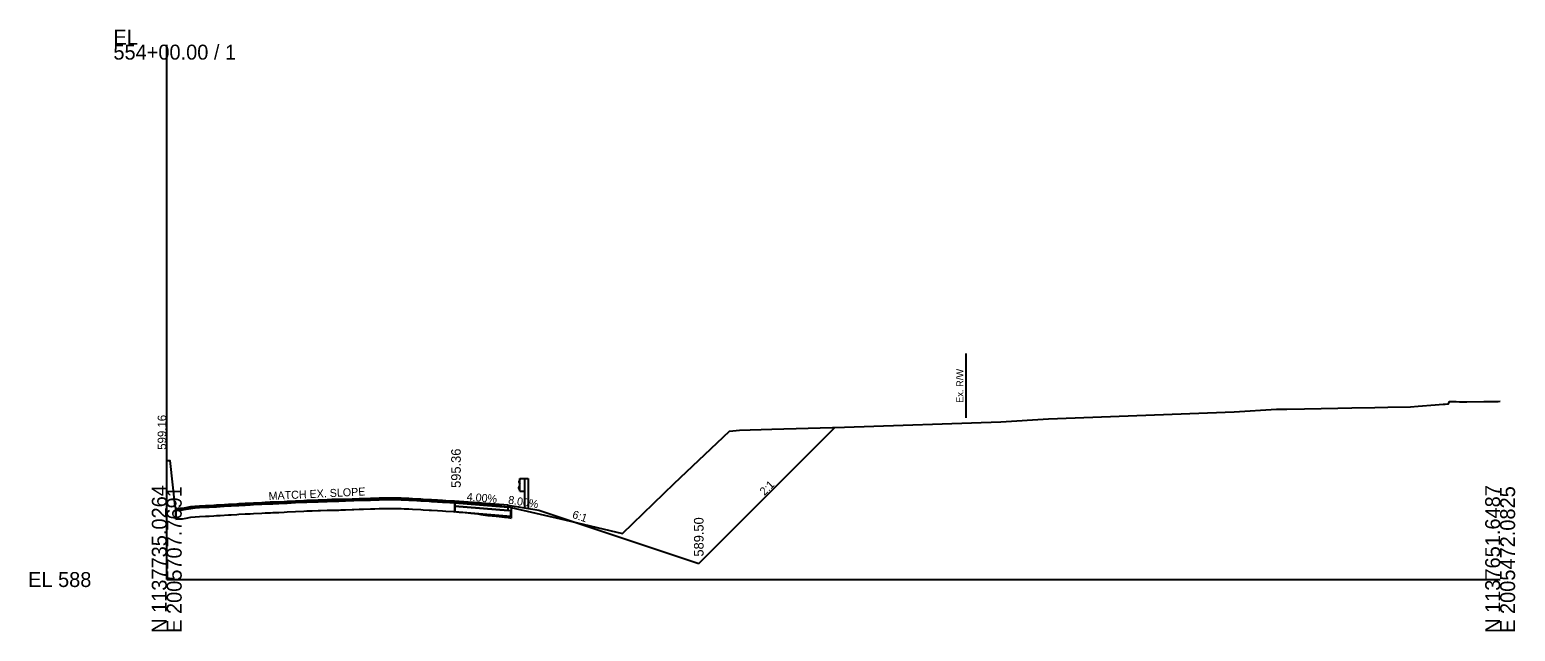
# Model space of a CAD drawing. Extents: x -201 to 2007062, y -213 to 1139737.
# Drawn here: x -25.7 to 252.8, y 7990.3 to 8103 of the extents above; entities that cross this region are included whole.
import ezdxf

# ---------------------------------------------------------------- set-up
doc = ezdxf.new("R2010")
doc.units = 0
for name, color, linetype in [('Default', 7, 'Continuous'), ('RD_GPK_XS_Cell', 7, 'Continuous'), ('RD_Sketch1', 7, 'Continuous'), ('RD_XS_Base', 7, 'Continuous'), ('RD_XS_EarthShd', 7, 'Continuous'), ('RD_XS_ExGround', 7, 'Continuous'), ('RD_XS_ExPaveRet', 7, 'Continuous'), ('RD_XS_ExRW', 7, 'Continuous'), ('RD_XS_GR', 7, 'Continuous'), ('RD_XS_PaveOvlay', 7, 'Continuous'), ('RD_XS_PaveShd', 7, 'Continuous'), ('RD_XS_TieSlope', 7, 'Continuous'), ('RD_XS_TX_Ditch', 7, 'Continuous'), ('RD_XS_TX_Elev_EX', 7, 'Continuous'), ('RD_XS_TX_Elev_PR', 7, 'Continuous'), ('RD_XS_TX_Slope', 7, 'Continuous')]:
    doc.layers.add(name, color=color, linetype=linetype)

msp = doc.modelspace()

# ---------------------------------------------------------------- linework, layer by layer
at = {"layer": 'RD_GPK_XS_Cell'}
for q in [(0, 8100.22), (250, 8000)]:
    msp.add_line((0, 8000), q, dxfattribs=at)
at = {"layer": 'RD_XS_Base'}
for points in [[(64, 8013.58), (54, 8014.38)], [(54, 8014.38), (54, 8013.72)], [(64.5, 8012.88), (64, 8012.92), (54, 8013.72)], [(54, 8013.72), (54, 8012.72)], [(54, 8013.72), (64, 8012.92)], [(64, 8012.92), (64, 8013.58)], [(54, 8012.72), (64.5, 8011.88)], [(64.5, 8011.88), (64.5, 8012.88)]]:
    msp.add_lwpolyline(points, dxfattribs=at)
at = {"layer": 'RD_XS_EarthShd'}
msp.add_lwpolyline([(64, 8013.91), (69.75, 8012.99)], dxfattribs=at)
at = {"layer": 'RD_XS_ExGround'}
msp.add_lwpolyline([(0, 8022.31), (0.57, 8022.33), (1.52, 8013.72), (1.68, 8013.32), (2.13, 8013.35), (2.94, 8013.39), (3.62, 8013.52), (4.52, 8013.66), (5.32, 8013.76), (6.11, 8013.8), (7.27, 8013.86), (7.97, 8013.9), (8.82, 8013.94), (9.3, 8013.97), (10.03, 8014.02), (11.59, 8014.11), (12.07, 8014.14), (13.16, 8014.21), (13.54, 8014.24), (14.73, 8014.29), (15.67, 8014.33), (16.29, 8014.37), (17.83, 8014.46), (18.45, 8014.51), (19.12, 8014.51), (19.43, 8014.53), (19.91, 8014.55), (21, 8014.58), (22.03, 8014.63), (22.56, 8014.66), (24.15, 8014.76), (25.7, 8014.84), (26.27, 8014.86), (27.26, 8014.88), (28.39, 8014.93), (28.83, 8014.94), (30.06, 8014.98), (30.48, 8015), (30.98, 8015.03), (32.25, 8015.03), (32.64, 8015.05), (33.53, 8015.09), (34.76, 8015.13), (35.1, 8015.14), (36.06, 8015.18), (36.88, 8015.21), (38.23, 8015.23), (39, 8015.25), (39.8, 8015.29), (41.37, 8015.31), (42.17, 8015.33), (42.49, 8015.34), (43.08, 8015.34), (43.97, 8015.29), (44.5, 8015.26), (45.37, 8015.22), (46.07, 8015.18), (47.64, 8015.1), (48.05, 8015.07), (49.2, 8015), (49.61, 8014.98), (50.77, 8014.92), (51.73, 8014.85), (52.34, 8014.81), (53.85, 8014.72), (54.8, 8014.65), (55.24, 8014.61), (55.97, 8014.56), (57.03, 8014.45), (58.3, 8014.32), (58.88, 8014.2), (60.22, 8014), (61.74, 8013.89), (62.34, 8013.83), (63.31, 8013.7), (64.03, 8013.61), (64.6, 8013.51), (74.66, 8011.16), (85.46, 8008.65), (95.15, 8018.02), (105.52, 8027.8), (107.41, 8027.99), (113.47, 8028.18), (127.06, 8028.55), (156.4, 8029.55), (165.31, 8030.11), (200.12, 8031.41), (208.06, 8031.9), (208.65, 8031.91), (209.36, 8031.92), (210.02, 8031.94), (213.3, 8032), (219.58, 8032.11), (222.18, 8032.16), (226.5, 8032.24), (228.92, 8032.28), (233.22, 8032.36), (234.63, 8032.47), (237.8, 8032.72), (239.34, 8032.84), (239.7, 8032.87), (240.34, 8032.92), (240.51, 8033.35), (241.23, 8033.35), (241.76, 8033.34), (242.35, 8033.32), (243.16, 8033.28), (243.73, 8033.27), (246.94, 8033.34), (247.58, 8033.33), (249.6, 8033.39), (250, 8033.41)], dxfattribs=at)
at = {"layer": 'RD_XS_ExPaveRet'}
for p, q in [((54, 8013.72), (54, 8014.38)), ((54, 8014.38), (54, 8014.38)), ((54, 8012.72), (54, 8013.72)), ((64.6, 8013.51), (64.6, 8011.51)), ((1.68, 8011.32), (1.68, 8013.32)), ((1.68, 8012.99), (1.68, 8011.32)), ((1.68, 8012.99), (1.68, 8012.99)), ((1.68, 8011.32), (2.13, 8011.35)), ((1.68, 8011.32), (2.13, 8011.35)), ((1.68, 8011.32), (1.68, 8011.32)), ((2.13, 8011.35), (2.94, 8011.39)), ((2.13, 8011.35), (2.94, 8011.39)), ((2.94, 8011.39), (3.62, 8011.52)), ((2.94, 8011.39), (3.62, 8011.52)), ((3.62, 8011.52), (4.52, 8011.66)), ((3.62, 8011.52), (4.52, 8011.66)), ((4.52, 8011.66), (5.32, 8011.76)), ((4.52, 8011.66), (5.32, 8011.76)), ((5.32, 8011.76), (6.11, 8011.8)), ((5.32, 8011.76), (6.11, 8011.8)), ((6.11, 8011.8), (7.27, 8011.86)), ((6.11, 8011.8), (7.27, 8011.86)), ((7.27, 8011.86), (7.97, 8011.9)), ((7.27, 8011.86), (7.97, 8011.9)), ((7.97, 8011.9), (8.82, 8011.94)), ((7.97, 8011.9), (8.82, 8011.94)), ((8.82, 8011.94), (9.3, 8011.97)), ((8.82, 8011.94), (9.3, 8011.97)), ((9.3, 8011.97), (10.03, 8012.02)), ((9.3, 8011.97), (10.03, 8012.02)), ((10.03, 8012.02), (11.59, 8012.11)), ((10.03, 8012.02), (11.59, 8012.11)), ((11.59, 8012.11), (12.07, 8012.14)), ((11.59, 8012.11), (12.07, 8012.14)), ((12.07, 8012.14), (13.16, 8012.21)), ((12.07, 8012.14), (13.16, 8012.21)), ((13.16, 8012.21), (13.54, 8012.24)), ((13.16, 8012.21), (13.54, 8012.24)), ((13.54, 8012.24), (14.73, 8012.29)), ((13.54, 8012.24), (14.73, 8012.29)), ((14.73, 8012.29), (15.67, 8012.33)), ((14.73, 8012.29), (15.67, 8012.33)), ((15.67, 8012.33), (16.29, 8012.37)), ((15.67, 8012.33), (16.29, 8012.37)), ((16.29, 8012.37), (17.83, 8012.46)), ((16.29, 8012.37), (17.83, 8012.46)), ((17.83, 8012.46), (18.45, 8012.51)), ((17.83, 8012.46), (18.45, 8012.51)), ((18.45, 8012.51), (19.12, 8012.51)), ((18.45, 8012.51), (19.12, 8012.51)), ((19.12, 8012.51), (19.43, 8012.53)), ((19.12, 8012.51), (19.43, 8012.53)), ((19.43, 8012.53), (19.91, 8012.55)), ((19.43, 8012.53), (19.91, 8012.55)), ((19.91, 8012.55), (21, 8012.58)), ((19.91, 8012.55), (21, 8012.58)), ((21, 8012.58), (22.03, 8012.63)), ((21, 8012.58), (22.03, 8012.63)), ((22.03, 8012.63), (22.56, 8012.66)), ((22.03, 8012.63), (22.56, 8012.66)), ((22.56, 8012.66), (24.15, 8012.76)), ((22.56, 8012.66), (24.15, 8012.76)), ((24.15, 8012.76), (25.7, 8012.84)), ((24.15, 8012.76), (25.7, 8012.84)), ((25.7, 8012.84), (26.27, 8012.86)), ((25.7, 8012.84), (26.27, 8012.86)), ((26.27, 8012.86), (27.26, 8012.88)), ((26.27, 8012.86), (27.26, 8012.88)), ((27.26, 8012.88), (28.39, 8012.93)), ((27.26, 8012.88), (28.39, 8012.93)), ((28.39, 8012.93), (28.83, 8012.94)), ((28.39, 8012.93), (28.83, 8012.94)), ((28.83, 8012.94), (30.06, 8012.98)), ((28.83, 8012.94), (30.06, 8012.98)), ((30.06, 8012.98), (30.48, 8013)), ((30.06, 8012.98), (30.48, 8013)), ((30.48, 8013), (30.98, 8013.03)), ((30.48, 8013), (30.98, 8013.03)), ((30.98, 8013.03), (32.25, 8013.03)), ((30.98, 8013.03), (32.25, 8013.03)), ((32.25, 8013.03), (32.64, 8013.05)), ((32.25, 8013.03), (32.64, 8013.05)), ((32.64, 8013.05), (33.53, 8013.09)), ((32.64, 8013.05), (33.53, 8013.09)), ((33.53, 8013.09), (34.76, 8013.13)), ((33.53, 8013.09), (34.76, 8013.13)), ((34.76, 8013.13), (35.1, 8013.14)), ((34.76, 8013.13), (35.1, 8013.14)), ((35.1, 8013.14), (36.06, 8013.18)), ((35.1, 8013.14), (36.06, 8013.18)), ((36.06, 8013.18), (36.88, 8013.21)), ((36.06, 8013.18), (36.88, 8013.21)), ((36.88, 8013.21), (38.23, 8013.23)), ((36.88, 8013.21), (38.23, 8013.23)), ((38.23, 8013.23), (39, 8013.25)), ((38.23, 8013.23), (39, 8013.25)), ((39, 8013.25), (39.8, 8013.29)), ((39, 8013.25), (39.8, 8013.29)), ((39.8, 8013.29), (41.37, 8013.31)), ((39.8, 8013.29), (41.37, 8013.31)), ((41.37, 8013.31), (42.17, 8013.33)), ((41.37, 8013.31), (42.17, 8013.33)), ((42.17, 8013.33), (42.49, 8013.34)), ((42.17, 8013.33), (42.49, 8013.34)), ((42.49, 8013.34), (43.08, 8013.34)), ((42.49, 8013.34), (43.08, 8013.34)), ((43.08, 8013.34), (43.97, 8013.29)), ((43.08, 8013.34), (43.97, 8013.29)), ((43.97, 8013.29), (44.5, 8013.26)), ((43.97, 8013.29), (44.5, 8013.26)), ((44.5, 8013.26), (45.37, 8013.22)), ((44.5, 8013.26), (45.37, 8013.22)), ((45.37, 8013.22), (46.07, 8013.18)), ((45.37, 8013.22), (46.07, 8013.18)), ((46.07, 8013.18), (47.64, 8013.1)), ((46.07, 8013.18), (47.64, 8013.1)), ((47.64, 8013.1), (48.05, 8013.07)), ((47.64, 8013.1), (48.05, 8013.07)), ((48.05, 8013.07), (49.2, 8013)), ((48.05, 8013.07), (49.2, 8013)), ((49.2, 8013), (49.61, 8012.98)), ((49.2, 8013), (49.61, 8012.98)), ((49.61, 8012.98), (50.77, 8012.92)), ((49.61, 8012.98), (50.77, 8012.92)), ((50.77, 8012.92), (51.73, 8012.85)), ((50.77, 8012.92), (51.73, 8012.85)), ((51.73, 8012.85), (52.34, 8012.81)), ((51.73, 8012.85), (52.34, 8012.81)), ((52.34, 8012.81), (53.85, 8012.72)), ((52.34, 8012.81), (53.85, 8012.72)), ((53.85, 8012.72), (54.8, 8012.65)), ((53.85, 8012.72), (54, 8012.71)), ((54, 8012.72), (54, 8012.71)), ((54, 8012.71), (54, 8012.72)), ((54.8, 8012.65), (55.24, 8012.61)), ((55.24, 8012.61), (55.97, 8012.56)), ((55.97, 8012.56), (57.03, 8012.45)), ((57.03, 8012.45), (58.3, 8012.32)), ((58.3, 8012.32), (58.88, 8012.2)), ((58.88, 8012.2), (60.22, 8012)), ((60.22, 8012), (61.74, 8011.89)), ((61.74, 8011.89), (62.34, 8011.83)), ((62.34, 8011.83), (63.31, 8011.7)), ((63.31, 8011.7), (64.03, 8011.61)), ((64.03, 8011.61), (64.6, 8011.51))]:
    msp.add_line(p, q, dxfattribs=at)
msp.add_lwpolyline([(54, 8014.38), (53.85, 8014.39), (52.34, 8014.47), (51.73, 8014.51), (50.77, 8014.59), (49.61, 8014.65), (49.2, 8014.67), (48.05, 8014.74), (47.64, 8014.77), (46.07, 8014.85), (45.37, 8014.88), (44.5, 8014.93), (43.97, 8014.96), (43.08, 8015.01), (42.49, 8015), (42.17, 8015), (41.37, 8014.98), (39.8, 8014.95), (39, 8014.92), (38.23, 8014.9), (36.88, 8014.88), (36.06, 8014.85), (35.1, 8014.81), (34.76, 8014.8), (33.53, 8014.76), (32.64, 8014.72), (32.25, 8014.7), (30.98, 8014.7), (30.48, 8014.66), (30.06, 8014.65), (28.83, 8014.61), (28.39, 8014.59), (27.26, 8014.54), (26.27, 8014.52), (25.7, 8014.5), (24.15, 8014.43), (22.56, 8014.32), (22.03, 8014.29), (21, 8014.25), (19.91, 8014.21), (19.43, 8014.2), (19.12, 8014.18), (18.45, 8014.18), (17.83, 8014.13), (16.29, 8014.03), (15.67, 8014), (14.73, 8013.95), (13.54, 8013.9), (13.16, 8013.88), (12.07, 8013.81), (11.59, 8013.78), (10.03, 8013.69), (9.3, 8013.64), (8.82, 8013.61), (7.97, 8013.57), (7.27, 8013.53), (6.11, 8013.47), (5.32, 8013.43), (4.52, 8013.33), (3.62, 8013.19), (2.94, 8013.06), (2.13, 8013.01), (1.68, 8012.99)], dxfattribs=at)
at = {"layer": 'RD_XS_ExRW'}
msp.add_line((149.85, 8042.33), (149.85, 8030.33), dxfattribs=at)
at = {"layer": 'RD_XS_GR'}
for p, q in [((66.17, 8018.76), (66, 8018.36)), ((66, 8018.36), (66, 8018.26)), ((66, 8018.26), (66.17, 8017.86)), ((66, 8017.22), (66.17, 8017.62)), ((66, 8017.12), (66, 8017.22)), ((66.17, 8016.72), (66, 8017.12)), ((66.17, 8016.57), (66.17, 8018.91)), ((66.17, 8018.91), (67.08, 8018.91)), ((66.17, 8016.57), (67.08, 8016.57)), ((67.08, 8018.91), (67.08, 8013.41)), ((67.08, 8018.91), (67.75, 8018.91)), ((67.75, 8018.91), (67.75, 8013.3))]:
    msp.add_line(p, q, dxfattribs=at)
for centre, major_axis in [((66, 8013.59), (0, -0.02)), ((69.75, 8012.99), (0, -0.0204))]:
    msp.add_ellipse(centre, major_axis=major_axis, ratio=0.5, dxfattribs=at)
at = {"layer": 'RD_XS_PaveOvlay'}
for points in [[(1.68, 8013.32), (1.68, 8013.32), (2.13, 8013.35), (2.94, 8013.39), (3.62, 8013.52), (4.52, 8013.66), (5.32, 8013.76), (6.11, 8013.8), (7.27, 8013.86), (7.97, 8013.9), (8.82, 8013.94), (9.3, 8013.97), (10.03, 8014.02), (11.59, 8014.11), (12.07, 8014.14), (13.16, 8014.21), (13.54, 8014.24), (14.73, 8014.29), (15.67, 8014.33), (16.29, 8014.37), (17.83, 8014.46), (18.45, 8014.51), (19.12, 8014.51), (19.43, 8014.53), (19.91, 8014.55), (21, 8014.58), (22.03, 8014.63), (22.56, 8014.66), (24.15, 8014.76), (25.7, 8014.84), (26.27, 8014.86), (27.26, 8014.88), (28.39, 8014.93), (28.83, 8014.94), (30.06, 8014.98), (30.48, 8015), (30.98, 8015.03), (32.25, 8015.03), (32.64, 8015.05), (33.53, 8015.09), (34.76, 8015.13), (35.1, 8015.14), (36.06, 8015.18), (36.88, 8015.21), (38.23, 8015.23), (39, 8015.25), (39.8, 8015.29), (41.37, 8015.31), (42.17, 8015.33), (42.49, 8015.34), (43.08, 8015.34), (43.97, 8015.29), (44.5, 8015.26), (45.37, 8015.22), (46.07, 8015.18), (47.64, 8015.1), (48.05, 8015.07), (49.2, 8015), (49.61, 8014.98), (50.77, 8014.92), (51.73, 8014.85), (52.34, 8014.81), (53.85, 8014.72), (54, 8014.71)], [(1.68, 8012.99), (1.68, 8012.99), (2.13, 8013.01), (2.94, 8013.06), (3.62, 8013.19), (4.52, 8013.33), (5.32, 8013.43), (6.11, 8013.47), (7.27, 8013.53), (7.97, 8013.57), (8.82, 8013.61), (9.3, 8013.64), (10.03, 8013.69), (11.59, 8013.78), (12.07, 8013.81), (13.16, 8013.88), (13.54, 8013.9), (14.73, 8013.95), (15.67, 8014), (16.29, 8014.03), (17.83, 8014.13), (18.45, 8014.18), (19.12, 8014.18), (19.43, 8014.2), (19.91, 8014.21), (21, 8014.25), (22.03, 8014.29), (22.56, 8014.32), (24.15, 8014.43), (25.7, 8014.5), (26.27, 8014.52), (27.26, 8014.54), (28.39, 8014.59), (28.83, 8014.61), (30.06, 8014.65), (30.48, 8014.66), (30.98, 8014.7), (32.25, 8014.7), (32.64, 8014.72), (33.53, 8014.76), (34.76, 8014.8), (35.1, 8014.81), (36.06, 8014.85), (36.88, 8014.88), (38.23, 8014.9), (39, 8014.92), (39.8, 8014.95), (41.37, 8014.98), (42.17, 8015), (42.49, 8015), (43.08, 8015.01), (43.97, 8014.96), (44.5, 8014.93), (45.37, 8014.88), (46.07, 8014.85), (47.64, 8014.77), (48.05, 8014.74), (49.2, 8014.67), (49.61, 8014.65), (50.77, 8014.59), (51.73, 8014.51), (52.34, 8014.47), (53.85, 8014.39), (54, 8014.38)]]:
    msp.add_lwpolyline(points, dxfattribs=at)
at = {"layer": 'RD_XS_PaveShd'}
for points in [[(64, 8013.91), (54, 8014.71)], [(54, 8014.71), (54, 8014.38)], [(54, 8014.38), (64, 8013.58)], [(64, 8013.58), (64, 8013.91)]]:
    msp.add_lwpolyline(points, dxfattribs=at)
at = {"layer": 'RD_XS_TieSlope'}
msp.add_line((69.75, 8012.99), (99.75, 8002.99), dxfattribs=at)
msp.add_lwpolyline([(99.75, 8002.99), (125.26, 8028.5)], dxfattribs=at)

# ---------------------------------------------------------------- texts
at = {"layer": 'Default'}
msp.add_text('-', height=0.0001, dxfattribs=at).set_placement((0, 8000))
at = {"layer": 'RD_GPK_XS_Cell'}
for s, p in [('EL', (-10, 8100.22)), ('554+00.00 / 1', (-10, 8097.42)), ('EL 588', (-26, 7998.6))]:
    msp.add_text(s, height=2.8, dxfattribs=at).set_placement(p)
for s, p in [('N 1137735.0264', (0, 7990)), ('E 2005707.7691', (2.8, 7990)), ('N 1137651.6487', (250, 7990)), ('E 2005472.0825', (252.8, 7990))]:
    msp.add_text(s, height=2.8, rotation=90, dxfattribs=at).set_placement(p)
at = {"layer": 'RD_Sketch1'}
for s, p in [('Exterior Boundary', (121.08, 8028.35)), ('LOC_C', (121.41, 8028.35)), ('Exterior Boundary', (53.44, 8014.66)), ('EP_X_R', (53.73, 8014.66)), ('EP_X2', (53.79, 8013.67)), ('EP_X1', (53.8, 8014.33)), ('ESP1_R', (63.73, 8013.53)), ('ESP_R', (63.77, 8013.86)), ('ES_R', (65.82, 8013.54)), ('EP_X3', (53.79, 8012.67)), ('ESP2_R', (63.73, 8012.87)), ('ESP4_R', (64.23, 8012.83)), ('ESP3_R', (64.23, 8011.83))]:
    msp.add_text(s, height=0.05, dxfattribs=at).set_placement(p)
at = {"layer": 'RD_XS_ExRW'}
msp.add_text('Ex. R/W ', height=1.3, rotation=90, dxfattribs=at).set_placement((149.35, 8033.1))
at = {"layer": 'RD_XS_TX_Ditch'}
msp.add_text('589.50', height=1.8, rotation=90, dxfattribs=at).set_placement((100.65, 8004.3))
at = {"layer": 'RD_XS_TX_Elev_EX'}
msp.add_text('599.16', height=1.6, rotation=90, dxfattribs=at).set_placement((-0.1, 8024.31))
at = {"layer": 'RD_XS_TX_Elev_PR'}
msp.add_text('595.36', height=1.8, rotation=90, dxfattribs=at).set_placement((55.13, 8017.17))
at = {"layer": 'RD_XS_TX_Slope'}
for s, rotation, p in [('MATCH EX. SLOPE', 2.7318, (19.13, 8014.9)), ('4.00%', 355.4261, (56.2, 8014.79)), ('2:1', 45, (112.07, 8015.67)), ('8.00%', 350.9097, (63.93, 8014.24)), ('6:1', 341.5651, (75.91, 8011.59))]:
    msp.add_text(s, height=1.5, rotation=rotation, dxfattribs=at).set_placement(p)

doc.saveas('drawing.dxf')
